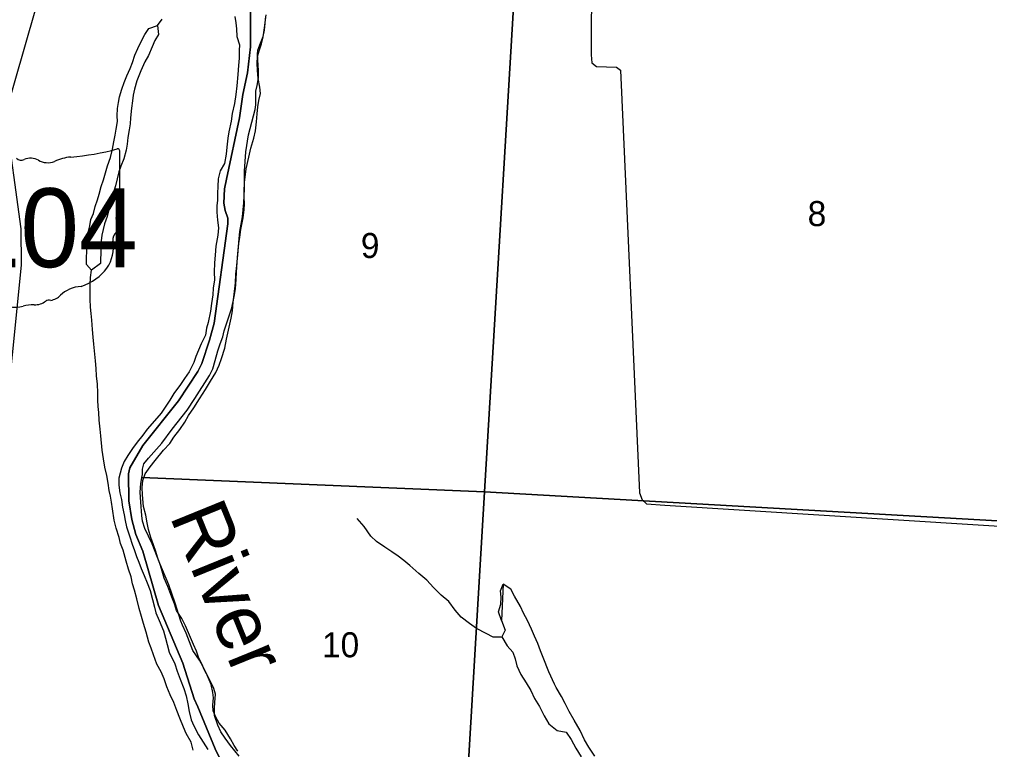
# Model space of a CAD drawing. Extents: x 1643459 to 2064572, y 425441 to 780708.
# Drawn here: x 1823182 to 1831742, y 553379 to 559825 of the extents above; entities that cross this region are included whole.
import ezdxf

# ---------------------------------------------------------------- set-up
doc = ezdxf.new("R2010")
doc.units = 0
for name, color, linetype in [('GM_X_Adjacent_County', 7, 'Continuous'), ('GM_X_City_Street', 7, 'Continuous'), ('GM_X_Major_River_Text', 7, 'Continuous'), ('GM_X_State_Route', 7, 'Continuous'), ('GM_X_State_Shield', 7, 'Continuous'), ('GM_X_Township_Subdivision_Text', 7, 'Continuous'), ('GM_X_Unincorporated_Text', 7, 'Continuous'), ('GM_X_US_Route', 7, 'Continuous'), ('RD_X_Text', 7, 'Continuous'), ('ST_Details', 7, 'Continuous')]:
    doc.layers.add(name, color=color, linetype=linetype)

msp = doc.modelspace()

# ---------------------------------------------------------------- linework, layer by layer
at = {"layer": 'GM_X_City_Street'}
for points in [[(1825034.5, 553127.9), (1824908.5, 553385.6), (1824755, 553755.5), (1824723.5, 553827.9), (1824623.6, 554143.3), (1824409.1, 554652), (1824270.3, 555132), (1824209.3, 555276.8), (1824174.2, 555411.4), (1824147.3, 555573.9), (1824144.7, 555812.5), (1824157.1, 555866.6), (1824270.1, 556062.3), (1824586.2, 556459), (1824755.6, 556716.5), (1824790, 556788.4), (1824859.2, 556994.4), (1824900.1, 557144.5), (1825021.4, 558019.8), (1825021.7, 558069.9), (1824996.2, 558138.2), (1824984.6, 558202.5), (1824991.4, 558328.7), (1825009.1, 558415.5), (1825123.1, 558955.3), (1825154.4, 559161.6), (1825195.5, 559351.8), (1825220.9, 559582.1), (1825221.3, 559963)], [(1825221.3, 559963), (1825220.9, 559582.1), (1825195.5, 559351.8), (1825154.4, 559161.6), (1825123.1, 558955.3), (1825009.1, 558415.5), (1824991.4, 558328.7), (1824984.6, 558202.5), (1824996.2, 558138.2), (1825021.7, 558069.9), (1825021.4, 558019.8), (1824900.1, 557144.5), (1824859.2, 556994.4), (1824790, 556788.4), (1824755.6, 556716.5), (1824586.2, 556459), (1824270.1, 556062.3), (1824157.1, 555866.6), (1824144.7, 555812.5), (1824147.3, 555573.9), (1824174.2, 555411.4), (1824209.3, 555276.8), (1824270.3, 555132), (1824409.1, 554652), (1824623.6, 554143.3), (1824723.5, 553827.9), (1824755, 553755.5), (1824908.5, 553385.6), (1825034.5, 553127.9)]]:
    msp.add_lwpolyline(points, dxfattribs=at)
at = {"layer": 'GM_X_Major_River_Text'}
for points in [[(1829118.8, 565097.9), (1828389.6, 563205.5), (1828348.8, 563093.6), (1828231.7, 560953.9), (1828225.4, 559512.8), (1828231, 559442.6), (1828272.7, 559408.2), (1828450.6, 559402.7), (1828484.4, 559376.4), (1828651.9, 555647), (1828675.4, 555584.7), (1828715.2, 555548.3), (1828875.3, 555538.2)], [(1828875.3, 555538.2), (1828876.8, 555538.1), (1833047.7, 555275.7), (1835762.5, 555094.8), (1836399.1, 555064.1)]]:
    msp.add_lwpolyline(points, dxfattribs=at)
at = {"layer": 'GM_X_State_Route'}
for points in [[(1827607.3, 561018.7), (1827284.7, 555653.9), (1824262.5, 555780.3), (1824266.7, 555808.3), (1824269, 555854.3), (1824279.3, 555902.2), (1824319.6, 555952), (1824438.4, 556083.2), (1824529.2, 556208.6), (1824662.2, 556375.8), (1824730.9, 556477.4), (1824858.2, 556682.6), (1824888.5, 556740.4), (1824909, 556814.3), (1824933.5, 556898.2), (1824953.9, 556960), (1824976.3, 557023.9), (1824988.6, 557075.8), (1825019.2, 557173.6), (1825055.9, 557277.4), (1825076.5, 557377.3), (1825088.9, 557445.2), (1825095.4, 557531.2), (1825097.8, 557593.1), (1825106.6, 557723.1), (1825126.1, 557953), (1825148.8, 558080.8), (1825161.6, 558206.8), (1825166.4, 558328.7), (1825167.4, 558484.7), (1825178.4, 558654.6), (1825203.4, 558806.5), (1825260.7, 559028.1), (1825269, 559070.1), (1825267.7, 559192.1), (1825280.1, 559242), (1825290.5, 559308), (1825290.8, 559372), (1825283.8, 559518), (1825286, 559552), (1825302.3, 559599.9), (1825332.7, 559673.7), (1825345.1, 559729.6), (1825351.5, 559791.6), (1825355.8, 559853.6)], [(1825109.5, 553365), (1825075.9, 553415.2), (1825044.2, 553475.4), (1824996.7, 553549.7), (1824945.1, 553614), (1824913.4, 553666.2), (1824891.7, 553722.4), (1824888.1, 553772.4), (1824894.5, 553836.3), (1824888.7, 553882.4), (1824873.2, 553952.5), (1824839.7, 554036.7), (1824802.2, 554110.9), (1824770.5, 554169.1), (1824713.1, 554255.5), (1824652, 554407.9), (1824620.4, 554478.1), (1824606.6, 554512.1), (1824555.6, 554670.5), (1824498.7, 554832.8), (1824419.8, 555021.3), (1824352.9, 555195.7), (1824289.7, 555330.1), (1824268.1, 555394.3), (1824260.4, 555444.3), (1824253.2, 555562.4), (1824247.8, 555652.4), (1824252.2, 555728.4), (1824258.4, 555760.3), (1824262.5, 555780.3), (1827284.7, 555653.9), (1827044.4, 551584.9)], [(1827044.4, 551584.9), (1827284.7, 555653.9), (1832852, 555339.3)]]:
    msp.add_lwpolyline(points, dxfattribs=at)
msp.add_lwpolyline([(1827607.3, 561018.7), (1833155.9, 560708), (1832852, 555339.3), (1827284.7, 555653.9)], close=True, dxfattribs=at)
at = {"layer": 'GM_X_Township_Subdivision_Text'}
msp.add_line((1827449.8, 554840.8), (1827435.8, 554520.2), dxfattribs=at)
for points in [[(1827852.1, 554067), (1827801.9, 554192), (1827778.2, 554252.4), (1827754.6, 554314.8), (1827727, 554379.2), (1827701.3, 554441.6), (1827663.8, 554518.1), (1827630.2, 554584.5), (1827602.5, 554642.9), (1827549, 554733.5), (1827517.4, 554796), (1827449.8, 554840.8)], [(1827435.8, 554520.2), (1827467.2, 554433), (1827438.8, 554375), (1827486.4, 554296.4), (1827536, 554237.9), (1827555.7, 554179.6), (1827569.3, 554119.3), (1827606.9, 554040.8), (1827654.4, 553968.2), (1827694, 553899.7), (1827725.6, 553831.3), (1827769.2, 553758.8), (1827810.7, 553678.2), (1827852.3, 553605.7), (1827928, 553547), (1828006, 553534.5), (1828049.6, 553468), (1828091.1, 553393.4), (1828138.7, 553316.9)], [(1827903.5, 553956.8), (1827852.1, 554067)], [(1828258.8, 553320.1), (1828205.2, 553400.8), (1828167.6, 553465.2), (1828128.1, 553547.8), (1828076.6, 553638.4), (1828031.1, 553714.9), (1827997.5, 553785.4), (1827965.9, 553847.8), (1827918.3, 553928.4), (1827903.5, 553956.8)]]:
    msp.add_lwpolyline(points, dxfattribs=at)
at = {"layer": 'GM_X_Unincorporated_Text'}
for points in [[(1824904, 553679.4), (1824902.4, 553745.6), (1824906.7, 553795.7), (1824913.1, 553867.8), (1824897.5, 553920), (1824850.1, 554014.6), (1824814.6, 554081), (1824791, 554135.3), (1824765.3, 554187.6), (1824743.7, 554247.9), (1824718.1, 554306.2), (1824674.9, 554410.7), (1824647.3, 554471), (1824613.7, 554535.4), (1824568.2, 554607.9), (1824550.6, 554666.2), (1824527, 554724.5), (1824491.7, 554818.9), (1824460.2, 554891.3), (1824440.6, 554955.6), (1824423, 555013.9), (1824403.4, 555068.1), (1824385.8, 555128.4), (1824364.2, 555186.7), (1824340.6, 555251), (1824321.1, 555321.3), (1824309.5, 555381.5), (1824295.9, 555447.8), (1824276.4, 555524.1), (1824267.1, 555628.4), (1824263.5, 555692.6), (1824271.8, 555754.7), (1824290.2, 555812.7), (1824334.5, 555874.5), (1824380.8, 555930.3), (1824453.3, 556022), (1824509.6, 556081.8), (1824543.9, 556135.7), (1824598.2, 556203.5), (1824642.6, 556269.3), (1824672.9, 556327.3), (1824719.3, 556395.1), (1824771.7, 556474.9), (1824824.1, 556558.8), (1824866.5, 556630.7), (1824915, 556706.5), (1824945.3, 556772.5), (1824963.7, 556832.5), (1824994.2, 556922.5), (1825008.7, 557002.6), (1825027.2, 557082.7), (1825037.5, 557134.7), (1825049.8, 557188.8), (1825062.2, 557252.8), (1825068.6, 557328.9), (1825077.1, 557395), (1825087.7, 557499.2), (1825090.2, 557575.4), (1825096.5, 557625.5), (1825102.8, 557683.6), (1825109.2, 557747.7), (1825117.8, 557847.8), (1825126.2, 557901.9), (1825134.6, 557970), (1825155.2, 558072.1), (1825165.7, 558146.2), (1825168, 558196.3), (1825164.3, 558254.5), (1825164.6, 558304.6), (1825167.2, 558386.8), (1825175.6, 558456.9), (1825181.9, 558507), (1825204.5, 558609.1), (1825225, 558689.1), (1825249.5, 558777.2), (1825263.9, 558841.2), (1825272.4, 558919.3), (1825278.8, 558991.5), (1825285.2, 559051.6), (1825295.5, 559107.6), (1825309.9, 559171.7), (1825304.3, 559227.8), (1825288.7, 559302.1), (1825281.2, 559374.4), (1825279.6, 559440.5), (1825282, 559494.6), (1825298.3, 559546.7), (1825316.6, 559608.7), (1825333, 559670.7), (1825341.4, 559730.8), (1825349.7, 559792.9), (1825358.2, 559865)], [(1825082.5, 559850.8), (1825092.1, 559794.6), (1825095.8, 559742.5), (1825101.3, 559674.3), (1825122.8, 559600), (1825120.5, 559549.9), (1825120.1, 559483.7), (1825115.7, 559417.6), (1825109.2, 559337.4), (1825100.6, 559239.3), (1825092.1, 559161.1), (1825079.7, 559083), (1825059.1, 558995), (1825048.7, 558924.9), (1825030.1, 558830.8), (1825021.8, 558776.7), (1825011.3, 558696.6), (1825006.9, 558634.5), (1824992.4, 558552.4), (1824954.1, 558488.5), (1824935.7, 558418.4), (1824933.2, 558348.3), (1824930.9, 558290.2), (1824928.5, 558230), (1824924.2, 558179.9), (1824923.8, 558121.8), (1824929.4, 558053.6), (1824938.9, 557983.4), (1824932.6, 557919.3), (1824916, 557823.2), (1824909.5, 557745), (1824903, 557674.9), (1824900.5, 557594.7), (1824902.1, 557524.5), (1824891.7, 557452.4), (1824887.3, 557392.3), (1824876.8, 557316.2), (1824866.4, 557248.1), (1824845.8, 557150), (1824833.5, 557098), (1824823.2, 557037.9), (1824786.7, 556962), (1824760.4, 556904), (1824738.1, 556850.1), (1824719.8, 556796.1), (1824679.3, 556714.1), (1824637, 556654.3), (1824602.7, 556602.4), (1824544.3, 556522.6), (1824510, 556462.7), (1824467.6, 556400.8), (1824431.4, 556349), (1824375, 556281.2), (1824308.6, 556207.5), (1824270.4, 556155.6), (1824222, 556093.8), (1824179.7, 556035.9), (1824137.4, 555974.1), (1824105.1, 555922.2), (1824082.8, 555862.2), (1824060.3, 555776.2), (1824059.9, 555712), (1824067.4, 555645.8), (1824081, 555585.5), (1824092.6, 555519.3), (1824106.2, 555451.1), (1824113.8, 555400.9), (1824127.5, 555344.7), (1824154.9, 555258.3), (1824176.5, 555194), (1824196.1, 555135.7), (1824215.7, 555083.4), (1824235.4, 555033.2), (1824255, 554978.9), (1824282.6, 554916.6), (1824310.1, 554850.2), (1824335.7, 554783.9), (1824357.1, 554703.6), (1824372.7, 554635.3), (1824386.3, 554585.1), (1824415.9, 554518.7), (1824453.3, 554428.3), (1824470.8, 554362), (1824486.5, 554305.8), (1824504, 554239.5), (1824553.3, 554136.9), (1824574.9, 554072.6), (1824600.4, 554002.3)], [(1824600.4, 554002.3), (1824631.8, 553917.8), (1824653.4, 553853.5), (1824668.9, 553783.3), (1824678.5, 553717), (1824698, 553640.7), (1824721.6, 553590.5), (1824763.1, 553510), (1824802.6, 553443.6), (1824844.1, 553379.1)], [(1825121.4, 553321.1), (1825044.1, 553415.8), (1824996.6, 553480.3), (1824959, 553536.7), (1824931.4, 553595), (1824904, 553679.4)]]:
    msp.add_lwpolyline(points, dxfattribs=at)
at = {"layer": 'GM_X_US_Route'}
for points in [[(1823912, 556023.7), (1823900.8, 556148.1), (1823895.2, 556206.3), (1823885.7, 556288.5), (1823882.2, 556354.7), (1823876.5, 556406.9), (1823874.9, 556465), (1823873.2, 556527.2), (1823869.7, 556605.4), (1823862.2, 556679.6), (1823858.6, 556741.8), (1823853.1, 556810), (1823838, 556958.5), (1823832.4, 557018.6), (1823826.8, 557088.8), (1823819.4, 557169.1), (1823815.7, 557229.2), (1823810.1, 557285.4), (1823806.5, 557355.6), (1823805, 557425.8), (1823805.4, 557483.9), (1823809.7, 557546), (1823818.1, 557610.1), (1823774.5, 557662.6), (1823774.9, 557722.7), (1823777.2, 557774.8), (1823779.7, 557857), (1823786.2, 557931.1), (1823802.6, 558001.2), (1823812.9, 558057.2), (1823835.2, 558111.2), (1823849.6, 558173.3), (1823871.9, 558231.2), (1823884.2, 558281.3), (1823902.6, 558349.3), (1823925, 558407.3), (1823941.3, 558469.3), (1823959.7, 558533.4), (1823984.1, 558605.4), (1824002.6, 558679.4), (1824015, 558743.5), (1824027.3, 558801.5), (1824035.6, 558855.6), (1824046.1, 558923.7), (1824044.4, 558973.8), (1824046.8, 559038), (1824055.1, 559092), (1824065.4, 559142.1), (1824085.8, 559210.1), (1824106.1, 559268.1), (1824130.5, 559326.1), (1824158.8, 559392), (1824179.1, 559444), (1824201.5, 559508), (1824227.9, 559568), (1824254.2, 559623.9), (1824288.6, 559691.9), (1824322.8, 559743.8), (1824400.9, 559769.3), (1824441.2, 559825.2)], [(1824400.9, 559769.3), (1824408.4, 559691), (1824376.1, 559639.2), (1824351.8, 559581.2), (1824319.3, 559507.2), (1824289, 559451.3), (1824252.6, 559371.3), (1824218.1, 559283.4), (1824195.7, 559209.3), (1824185.3, 559157.3), (1824179, 559105.2), (1824170.6, 559041.1), (1824162.1, 558955), (1824157.8, 558902.9), (1824149.5, 558848.8), (1824139.1, 558782.7), (1824132.7, 558722.6), (1824122.4, 558670.6), (1824101.9, 558594.5), (1824075.5, 558528.6), (1824059.3, 558478.5), (1824042.9, 558416.5), (1824028.5, 558354.5), (1824008.1, 558288.5), (1823989.8, 558224.4), (1823967.2, 558134.4), (1823956.9, 558084.3), (1823932.5, 558020.3), (1823909.9, 557920.2), (1823901.6, 557870.2), (1823899.2, 557796), (1823898.4, 557669.7), (1823818.1, 557610.1)], [(1824714.3, 553374), (1824696.8, 553446.3), (1824653.3, 553520.8), (1824629.7, 553577), (1824598.2, 553655.4), (1824570.7, 553723.8), (1824543.2, 553794.2), (1824511.6, 553862.5), (1824482.1, 553932.9), (1824458.6, 554005.2), (1824431, 554065.6), (1824393.5, 554132), (1824366.1, 554216.4), (1824344.5, 554274.6), (1824322.8, 554328.9), (1824299.4, 554417.3), (1824277.9, 554493.6), (1824258.3, 554553.9), (1824238.8, 554626.2), (1824217.4, 554710.5), (1824197.9, 554786.9), (1824180.2, 554841.1), (1824166.6, 554903.3), (1824145.1, 554971.7), (1824123.6, 555044), (1824096.2, 555140.4), (1824074.6, 555198.7), (1824063, 555252.9), (1824035.5, 555333.3), (1824018, 555405.5), (1824002.6, 555503.9), (1823995, 555562.1), (1823985.4, 555616.3), (1823973.7, 555666.5), (1823964.1, 555730.7), (1823952.6, 555798.9), (1823935.1, 555873.2), (1823923.5, 555945.5), (1823912, 556023.7)], [(1827436.2, 554371.3), (1827360.9, 554370.3), (1827301.2, 554402.8), (1827213.6, 554447.5), (1827152, 554492), (1827078.4, 554548.7), (1827026.9, 554611.2), (1826969.5, 554687.8), (1826903.9, 554742.3), (1826834.4, 554808.9), (1826776.9, 554873.5), (1826707.4, 554934.1), (1826625.9, 555004.8), (1826574.3, 555047.3), (1826522.6, 555085.7), (1826468.9, 555126.2), (1826405.2, 555166.7), (1826333.6, 555215.3), (1826282, 555261.8), (1826224.6, 555348.4), (1826163.2, 555419)], [(1827435.8, 554520.2), (1827410.3, 554596.5), (1827430.7, 554662.5), (1827431.1, 554724.7), (1827427.4, 554780.8), (1827449.8, 554840.8)]]:
    msp.add_lwpolyline(points, dxfattribs=at)
at = {"layer": 'RD_X_Text'}
msp.add_lwpolyline([(1823042.5, 556071.6), (1823200.9, 557656.7), (1823198.1, 557974.8), (1823057.7, 558988.5), (1823405.4, 560199.2), (1823958.8, 564300.2), (1824447, 565363.5), (1825329.9, 566818.3), (1825559.6, 566956.6), (1826410.3, 567212.5), (1826567.8, 567227.7), (1826989.8, 567263.6), (1827302.7, 567317.7), (1827510.4, 567493.1), (1827616.6, 567666.6), (1827699.6, 567802.2), (1827716.5, 567861.8), (1827775.7, 568271), (1827843, 568736.6), (1827857.7, 568927.2), (1827043.4, 571990.5), (1826831.9, 580172)], dxfattribs=at)
at = {"layer": 'ST_Details'}
for p, q in [((1824066.5, 558111.3), (1824066.5, 558664.1)), ((1824066.4, 558111.5), (1824066.5, 558111.3))]:
    msp.add_line(p, q, dxfattribs=at)
for centre, major_axis, start_param, end_param in [((1823446.7, 560078.4), (1845.5, 0), 4.814394, 5.042369), ((1824047.2, 558666.4), (19.4, 0), 6.141152, 7.989035), ((1823198.7, 558627.4), (56.4, 0), 3.836095, 5.185415), ((1823281.5, 558505.3), (117.3, 0), 0.950623, 2.079405), ((1823432.9, 558672.8), (141.1, 0), 4.081561, 5.145723), ((1823682.1, 558315.2), (371.3, 0), 1.699011, 2.107814), ((1824062.1, 558070.8), (30, 0), 1.883978, 3.671073), ((1824045.9, 558109.2), (20.7, 0), 5.05454, 6.418171), ((1823871.3, 558000.9), (180, 0), 5.934695, 6.695948), ((1824136, 557880), (130.9, 0), 2.387724, 3.262537), ((1823550, 557809.7), (461.6, 0), 5.101752, 6.440018), ((1823744.7, 557266.4), (252.8, 0), 1.647645, 2.488434), ((1823424.4, 557460.7), (149.1, 0), 4.937069, 5.64225), ((1823141.6, 557496.9), (264.6, 0), 4.026481, 4.996735), ((1823294.4, 557131.5), (217.4, 0), 1.495662, 1.94098), ((1823313.8, 557417.7), (141, 0), 4.691044, 5.507374), ((1823441.3, 557315.4), (39.7, 0), 1.147584, 2.315152)]:
    msp.add_ellipse(centre, major_axis=major_axis, ratio=0.8, start_param=start_param, end_param=end_param, dxfattribs=at)

# ---------------------------------------------------------------- texts
at = {"layer": 'GM_X_Adjacent_County'}
for s, p in [('8', (1830136.7, 558000)), ('9', (1826194.3, 557718.4)), ('10', (1825851.1, 554194))]:
    msp.add_text(s, height=221, rotation=0.00001, dxfattribs=at).set_placement(p)
at = {"layer": 'GM_X_State_Shield'}
msp.add_text('River', height=500, rotation=292.13975, dxfattribs=at).set_placement((1824503.6, 555443))
at = {"layer": 'ST_Details'}
msp.add_text('104', height=696.1, dxfattribs=at).set_placement((1822672.2, 557637.6))

doc.saveas('drawing.dxf')
